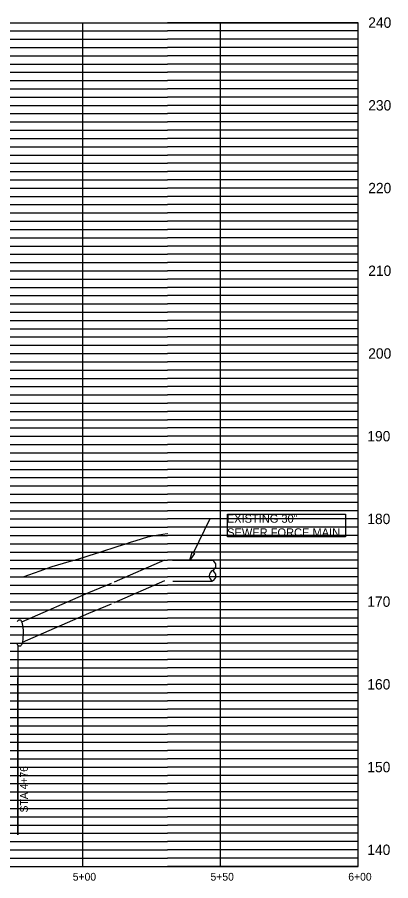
# Model space of a CAD drawing. Extents: x 1961446 to 1965364, y 798002 to 798458.
# Drawn here: x 1965228.5 to 1965364.1, y 798002.3 to 798315.4 of the extents above; entities that cross this region are included whole.
import ezdxf

# ---------------------------------------------------------------- set-up
doc = ezdxf.new("R2010")
doc.units = 0
for name, color, linetype in [('_C3D-PRSR-ANNO', 7, 'Continuous'), ('C-ANNO-SUBT', 7, 'Continuous'), ('C-GRID-MEDI', 7, 'Continuous'), ('C-GRID-THIN', 7, 'Continuous'), ('C-PROF-EXST', 7, 'Continuous'), ('C-SSWR-FMAN-FTTG', 7, 'Continuous'), ('C-SSWR-FMAN-PIPE', 7, 'Continuous'), ('C-UTIL-FITT-ANNO', 7, 'Continuous')]:
    doc.layers.add(name, color=color, linetype=linetype)

msp = doc.modelspace()

# ---------------------------------------------------------------- linework, layer by layer
at = {"layer": '_C3D-PRSR-ANNO'}
for points in [[(1965284.93, 798118.48), (1965299.41, 798118.48)], [(1965285.03, 798110.98), (1965299.41, 798110.98)]]:
    msp.add_lwpolyline(points, dxfattribs=at)
for centre, start, end in [((1965298.58, 798116.61), 293.818, 66.182), ((1965300.24, 798112.86), 113.818, 246.182), ((1965298.58, 798112.86), 293.818, 66.182)]:
    msp.add_arc(centre, 2.05, start, end, dxfattribs=at)
at = {"layer": 'C-GRID-MEDI'}
for points in [[(1964702.28, 798313.48), (1965352.28, 798313.48)], [(1964752.28, 798313.48), (1965283.11, 798313.48)], [(1965252.28, 798007.48), (1965252.28, 798313.48)], [(1965352.28, 798313.48), (1965283.11, 798313.48)], [(1965302.28, 798007.48), (1965302.28, 798313.48)], [(1965352.28, 798007.48), (1965352.28, 798313.48)], [(1965352.28, 798007.48), (1965352.28, 798313.48)], [(1964752.28, 798283.48), (1965283.11, 798283.48)], [(1965352.28, 798283.48), (1965283.11, 798283.48)], [(1964752.28, 798253.48), (1965283.11, 798253.48)], [(1965352.28, 798253.48), (1965283.11, 798253.48)], [(1964752.28, 798223.48), (1965283.11, 798223.48)], [(1965352.28, 798223.48), (1965283.11, 798223.48)], [(1964752.28, 798193.48), (1965283.11, 798193.48)], [(1965352.28, 798193.48), (1965283.11, 798193.48)], [(1964752.28, 798163.48), (1965283.11, 798163.48)], [(1965352.28, 798163.48), (1965283.11, 798163.48)], [(1964752.28, 798133.48), (1965283.11, 798133.48)], [(1965352.28, 798133.48), (1965283.11, 798133.48)], [(1964752.28, 798103.48), (1965283.11, 798103.48)], [(1965352.28, 798103.48), (1965283.11, 798103.48)], [(1964752.28, 798073.48), (1965283.11, 798073.48)], [(1965352.28, 798073.48), (1965283.11, 798073.48)], [(1964752.28, 798043.48), (1965283.11, 798043.48)], [(1965352.28, 798043.48), (1965283.11, 798043.48)], [(1964752.28, 798013.48), (1965283.11, 798013.48)], [(1965352.28, 798013.48), (1965283.11, 798013.48)], [(1964702.28, 798007.48), (1965352.28, 798007.48)], [(1964752.28, 798007.48), (1965283.11, 798007.48)], [(1965352.28, 798007.48), (1965283.11, 798007.48)]]:
    msp.add_lwpolyline(points, dxfattribs=at)
at = {"layer": 'C-GRID-THIN'}
for points in [[(1964752.28, 798310.48), (1965283.11, 798310.48)], [(1964752.28, 798307.48), (1965283.11, 798307.48)], [(1965352.28, 798310.48), (1965283.11, 798310.48)], [(1965352.28, 798307.48), (1965283.11, 798307.48)], [(1964752.28, 798304.48), (1965283.11, 798304.48)], [(1965352.28, 798304.48), (1965283.11, 798304.48)], [(1964752.28, 798301.48), (1965283.11, 798301.48)], [(1965352.28, 798301.48), (1965283.11, 798301.48)], [(1964752.28, 798298.48), (1965283.11, 798298.48)], [(1965352.28, 798298.48), (1965283.11, 798298.48)], [(1964752.28, 798295.48), (1965283.11, 798295.48)], [(1965352.28, 798295.48), (1965283.11, 798295.48)], [(1964752.28, 798292.48), (1965283.11, 798292.48)], [(1965352.28, 798292.48), (1965283.11, 798292.48)], [(1964752.28, 798289.48), (1965283.11, 798289.48)], [(1965352.28, 798289.48), (1965283.11, 798289.48)], [(1964752.28, 798286.48), (1965283.11, 798286.48)], [(1965352.28, 798286.48), (1965283.11, 798286.48)], [(1964752.28, 798280.48), (1965283.11, 798280.48)], [(1965352.28, 798280.48), (1965283.11, 798280.48)], [(1964752.28, 798277.48), (1965283.11, 798277.48)], [(1965352.28, 798277.48), (1965283.11, 798277.48)], [(1964752.28, 798274.48), (1965283.11, 798274.48)], [(1965352.28, 798274.48), (1965283.11, 798274.48)], [(1964752.28, 798271.48), (1965283.11, 798271.48)], [(1965352.28, 798271.48), (1965283.11, 798271.48)], [(1964752.28, 798268.48), (1965283.11, 798268.48)], [(1965352.28, 798268.48), (1965283.11, 798268.48)], [(1964752.28, 798265.48), (1965283.11, 798265.48)], [(1965352.28, 798265.48), (1965283.11, 798265.48)], [(1964752.28, 798262.48), (1965283.11, 798262.48)], [(1965352.28, 798262.48), (1965283.11, 798262.48)], [(1964752.28, 798259.48), (1965283.11, 798259.48)], [(1965352.28, 798259.48), (1965283.11, 798259.48)], [(1964752.28, 798256.48), (1965283.11, 798256.48)], [(1965352.28, 798256.48), (1965283.11, 798256.48)], [(1964752.28, 798250.48), (1965283.11, 798250.48)], [(1965352.28, 798250.48), (1965283.11, 798250.48)], [(1964752.28, 798247.48), (1965283.11, 798247.48)], [(1965352.28, 798247.48), (1965283.11, 798247.48)], [(1964752.28, 798244.48), (1965283.11, 798244.48)], [(1965352.28, 798244.48), (1965283.11, 798244.48)], [(1964752.28, 798241.48), (1965283.11, 798241.48)], [(1965352.28, 798241.48), (1965283.11, 798241.48)], [(1964752.28, 798238.48), (1965283.11, 798238.48)], [(1964752.28, 798235.48), (1965283.11, 798235.48)], [(1965352.28, 798238.48), (1965283.11, 798238.48)], [(1965352.28, 798235.48), (1965283.11, 798235.48)], [(1964752.28, 798232.48), (1965283.11, 798232.48)], [(1965352.28, 798232.48), (1965283.11, 798232.48)], [(1964752.28, 798229.48), (1965283.11, 798229.48)], [(1965352.28, 798229.48), (1965283.11, 798229.48)], [(1964752.28, 798226.48), (1965283.11, 798226.48)], [(1965352.28, 798226.48), (1965283.11, 798226.48)], [(1964752.28, 798220.48), (1965283.11, 798220.48)], [(1965352.28, 798220.48), (1965283.11, 798220.48)], [(1964752.28, 798217.48), (1965283.11, 798217.48)], [(1965352.28, 798217.48), (1965283.11, 798217.48)], [(1964752.28, 798214.48), (1965283.11, 798214.48)], [(1965352.28, 798214.48), (1965283.11, 798214.48)], [(1964752.28, 798211.48), (1965283.11, 798211.48)], [(1965352.28, 798211.48), (1965283.11, 798211.48)], [(1964752.28, 798208.48), (1965283.11, 798208.48)], [(1965352.28, 798208.48), (1965283.11, 798208.48)], [(1964752.28, 798205.48), (1965283.11, 798205.48)], [(1965352.28, 798205.48), (1965283.11, 798205.48)], [(1964752.28, 798202.48), (1965283.11, 798202.48)], [(1965352.28, 798202.48), (1965283.11, 798202.48)], [(1964752.28, 798199.48), (1965283.11, 798199.48)], [(1965352.28, 798199.48), (1965283.11, 798199.48)], [(1964752.28, 798196.48), (1965283.11, 798196.48)], [(1965352.28, 798196.48), (1965283.11, 798196.48)], [(1964752.28, 798190.48), (1965283.11, 798190.48)], [(1965352.28, 798190.48), (1965283.11, 798190.48)], [(1964752.28, 798187.48), (1965283.11, 798187.48)], [(1965352.28, 798187.48), (1965283.11, 798187.48)], [(1964752.28, 798184.48), (1965283.11, 798184.48)], [(1965352.28, 798184.48), (1965283.11, 798184.48)], [(1964752.28, 798181.48), (1965283.11, 798181.48)], [(1965352.28, 798181.48), (1965283.11, 798181.48)], [(1964752.28, 798178.48), (1965283.11, 798178.48)], [(1965352.28, 798178.48), (1965283.11, 798178.48)], [(1964752.28, 798175.48), (1965283.11, 798175.48)], [(1965352.28, 798175.48), (1965283.11, 798175.48)], [(1964752.28, 798172.48), (1965283.11, 798172.48)], [(1965352.28, 798172.48), (1965283.11, 798172.48)], [(1964752.28, 798169.48), (1965283.11, 798169.48)], [(1964752.28, 798166.48), (1965283.11, 798166.48)], [(1965352.28, 798169.48), (1965283.11, 798169.48)], [(1965352.28, 798166.48), (1965283.11, 798166.48)], [(1964752.28, 798160.48), (1965283.11, 798160.48)], [(1965352.28, 798160.48), (1965283.11, 798160.48)], [(1964752.28, 798157.48), (1965283.11, 798157.48)], [(1965352.28, 798157.48), (1965283.11, 798157.48)], [(1964752.28, 798154.48), (1965283.11, 798154.48)], [(1965352.28, 798154.48), (1965283.11, 798154.48)], [(1964752.28, 798151.48), (1965283.11, 798151.48)], [(1965352.28, 798151.48), (1965283.11, 798151.48)], [(1964752.28, 798148.48), (1965283.11, 798148.48)], [(1965352.28, 798148.48), (1965283.11, 798148.48)], [(1964752.28, 798145.48), (1965283.11, 798145.48)], [(1965352.28, 798145.48), (1965283.11, 798145.48)], [(1964752.28, 798142.48), (1965283.11, 798142.48)], [(1965352.28, 798142.48), (1965283.11, 798142.48)], [(1964752.28, 798139.48), (1965283.11, 798139.48)], [(1965352.28, 798139.48), (1965283.11, 798139.48)], [(1964752.28, 798136.48), (1965283.11, 798136.48)], [(1965352.28, 798136.48), (1965283.11, 798136.48)], [(1964752.28, 798130.48), (1965283.11, 798130.48)], [(1965352.28, 798130.48), (1965283.11, 798130.48)], [(1964752.28, 798127.48), (1965283.11, 798127.48)], [(1965352.28, 798127.48), (1965283.11, 798127.48)], [(1964752.28, 798124.48), (1965283.11, 798124.48)], [(1965352.28, 798124.48), (1965283.11, 798124.48)], [(1964752.28, 798121.48), (1965283.11, 798121.48)], [(1965352.28, 798121.48), (1965283.11, 798121.48)], [(1964752.28, 798118.48), (1965283.11, 798118.48)], [(1965352.28, 798118.48), (1965283.11, 798118.48)], [(1964752.28, 798115.48), (1965283.11, 798115.48)], [(1965352.28, 798115.48), (1965283.11, 798115.48)], [(1964752.28, 798112.48), (1965283.11, 798112.48)], [(1965352.28, 798112.48), (1965283.11, 798112.48)], [(1964752.28, 798109.48), (1965283.11, 798109.48)], [(1965352.28, 798109.48), (1965283.11, 798109.48)], [(1964752.28, 798106.48), (1965283.11, 798106.48)], [(1965352.28, 798106.48), (1965283.11, 798106.48)], [(1964752.28, 798100.48), (1965283.11, 798100.48)], [(1965352.28, 798100.48), (1965283.11, 798100.48)], [(1964752.28, 798097.48), (1965283.11, 798097.48)], [(1964752.28, 798094.48), (1965283.11, 798094.48)], [(1965352.28, 798097.48), (1965283.11, 798097.48)], [(1965352.28, 798094.48), (1965283.11, 798094.48)], [(1964752.28, 798091.48), (1965283.11, 798091.48)], [(1965352.28, 798091.48), (1965283.11, 798091.48)], [(1964752.28, 798088.48), (1965283.11, 798088.48)], [(1965352.28, 798088.48), (1965283.11, 798088.48)], [(1964752.28, 798085.48), (1965283.11, 798085.48)], [(1965352.28, 798085.48), (1965283.11, 798085.48)], [(1964752.28, 798082.48), (1965283.11, 798082.48)], [(1965352.28, 798082.48), (1965283.11, 798082.48)], [(1964752.28, 798079.48), (1965283.11, 798079.48)], [(1965352.28, 798079.48), (1965283.11, 798079.48)], [(1964752.28, 798076.48), (1965283.11, 798076.48)], [(1965352.28, 798076.48), (1965283.11, 798076.48)], [(1964752.28, 798070.48), (1965283.11, 798070.48)], [(1965352.28, 798070.48), (1965283.11, 798070.48)], [(1964752.28, 798067.48), (1965283.11, 798067.48)], [(1965352.28, 798067.48), (1965283.11, 798067.48)], [(1964752.28, 798064.48), (1965283.11, 798064.48)], [(1965352.28, 798064.48), (1965283.11, 798064.48)], [(1964752.28, 798061.48), (1965283.11, 798061.48)], [(1965352.28, 798061.48), (1965283.11, 798061.48)], [(1964752.28, 798058.48), (1965283.11, 798058.48)], [(1965352.28, 798058.48), (1965283.11, 798058.48)], [(1964752.28, 798055.48), (1965283.11, 798055.48)], [(1965352.28, 798055.48), (1965283.11, 798055.48)], [(1964752.28, 798052.48), (1965283.11, 798052.48)], [(1965352.28, 798052.48), (1965283.11, 798052.48)], [(1964752.28, 798049.48), (1965283.11, 798049.48)], [(1965352.28, 798049.48), (1965283.11, 798049.48)], [(1964752.28, 798046.48), (1965283.11, 798046.48)], [(1965352.28, 798046.48), (1965283.11, 798046.48)], [(1964752.28, 798040.48), (1965283.11, 798040.48)], [(1965352.28, 798040.48), (1965283.11, 798040.48)], [(1964752.28, 798037.48), (1965283.11, 798037.48)], [(1965352.28, 798037.48), (1965283.11, 798037.48)], [(1964752.28, 798034.48), (1965283.11, 798034.48)], [(1965352.28, 798034.48), (1965283.11, 798034.48)], [(1964752.28, 798031.48), (1965283.11, 798031.48)], [(1965352.28, 798031.48), (1965283.11, 798031.48)], [(1964752.28, 798028.48), (1965283.11, 798028.48)], [(1965352.28, 798028.48), (1965283.11, 798028.48)], [(1964752.28, 798025.48), (1965283.11, 798025.48)], [(1964752.28, 798022.48), (1965283.11, 798022.48)], [(1965352.28, 798025.48), (1965283.11, 798025.48)], [(1965352.28, 798022.48), (1965283.11, 798022.48)], [(1964752.28, 798019.48), (1965283.11, 798019.48)], [(1965352.28, 798019.48), (1965283.11, 798019.48)], [(1964752.28, 798016.48), (1965283.11, 798016.48)], [(1965352.28, 798016.48), (1965283.11, 798016.48)], [(1964752.28, 798010.48), (1965283.11, 798010.48)], [(1965352.28, 798010.48), (1965283.11, 798010.48)]]:
    msp.add_lwpolyline(points, dxfattribs=at)
at = {"layer": 'C-PROF-EXST'}
for points in [[(1965271.63, 798125.65), (1965275.88, 798126.96)], [(1965275.88, 798126.96), (1965278.23, 798127.48)], [(1965278.23, 798127.48), (1965282.98, 798128.16)], [(1965282.98, 798128.16), (1965283.11, 798128.13)], [(1965258.46, 798121.48), (1965265.12, 798123.6)], [(1965265.12, 798123.6), (1965267.88, 798124.48)], [(1965267.88, 798124.48), (1965269.6, 798125.03)], [(1965269.6, 798125.03), (1965271.63, 798125.65)], [(1965251.23, 798119.16), (1965256.87, 798120.98)], [(1965256.87, 798120.98), (1965258.46, 798121.48)], [(1965241.19, 798116.22), (1965245.33, 798117.41)], [(1965245.33, 798117.41), (1965249.03, 798118.48)], [(1965249.03, 798118.48), (1965249.71, 798118.68)], [(1965249.71, 798118.68), (1965251.23, 798119.16)], [(1965230.63, 798112.48), (1965236.89, 798114.72)], [(1965236.89, 798114.72), (1965239.09, 798115.48)], [(1965239.09, 798115.48), (1965241.19, 798116.22)], [(1965228.48, 798112.47), (1965230.55, 798112.47)], [(1965230.55, 798112.47), (1965230.59, 798112.47)], [(1965230.59, 798112.47), (1965230.63, 798112.48)]]:
    msp.add_lwpolyline(points, dxfattribs=at)
at = {"layer": 'C-SSWR-FMAN-FTTG'}
for points in [[(1965228.63, 798096.42), (1965228.49, 798096.12)], [(1965228.83, 798096.67), (1965228.63, 798096.42)], [(1965229.03, 798096.76), (1965228.83, 798096.67)], [(1965229.7, 798096.76), (1965229.03, 798096.76)], [(1965229.91, 798096.67), (1965229.7, 798096.76)], [(1965230.11, 798096.42), (1965229.91, 798096.67)], [(1965230.29, 798096.02), (1965230.11, 798096.42)], [(1965230.46, 798095.47), (1965230.29, 798096.02)], [(1965230.59, 798094.8), (1965230.46, 798095.47)], [(1965230.7, 798094.04), (1965230.59, 798094.8)], [(1965230.76, 798093.2), (1965230.7, 798094.04)], [(1965230.73, 798090.59), (1965230.78, 798091.45)], [(1965230.79, 798092.33), (1965230.76, 798093.2)], [(1965230.78, 798091.45), (1965230.79, 798092.33)], [(1965230.2, 798087.98), (1965230.38, 798088.45)], [(1965230.38, 798088.45), (1965230.53, 798089.06)], [(1965230.53, 798089.06), (1965230.65, 798089.78)], [(1965230.65, 798089.78), (1965230.73, 798090.59)], [(1965228.49, 798088.1), (1965228.53, 798087.98)], [(1965228.53, 798087.98), (1965228.72, 798087.65)], [(1965228.72, 798087.65), (1965228.93, 798087.48)], [(1965228.93, 798087.48), (1965229.03, 798087.48)], [(1965229.03, 798087.48), (1965229.03, 798087.46)], [(1965229.03, 798087.46), (1965229.7, 798087.46)], [(1965229.7, 798087.46), (1965229.7, 798087.48)], [(1965229.7, 798087.48), (1965229.8, 798087.48)], [(1965229.8, 798087.48), (1965230.01, 798087.65)], [(1965230.01, 798087.65), (1965230.2, 798087.98)]]:
    msp.add_lwpolyline(points, dxfattribs=at)
at = {"layer": 'C-SSWR-FMAN-PIPE'}
for points in [[(1965263.79, 798110.71), (1965282.1, 798118.67)], [(1965254.51, 798106.81), (1965262.77, 798110.21)], [(1965263.79, 798103.21), (1965282.1, 798111.17)], [(1965230.2, 798096.23), (1965254.51, 798106.81)], [(1965254.51, 798099.31), (1965262.77, 798102.71)], [(1965230.47, 798088.85), (1965254.51, 798099.31)]]:
    msp.add_lwpolyline(points, dxfattribs=at)
at = {"layer": 'C-UTIL-FITT-ANNO'}
for points in [[(1965304.89, 798135.18), (1965347.66, 798135.18), (1965347.66, 798127.03), (1965304.89, 798127.03)], [(1965292.9, 798120.95), (1965291.12, 798118.48), (1965292, 798121.39)]]:
    msp.add_lwpolyline(points, close=True, dxfattribs=at)
for points in [[(1965292.45, 798121.17), (1965298.6, 798133.65)], [(1965298.6, 798133.65), (1965302.19, 798133.65)], [(1965228.76, 798087.46), (1965228.76, 798018.97)], [(1965228.76, 798018.97), (1965228.76, 798075.83)]]:
    msp.add_lwpolyline(points, dxfattribs=at)

# ---------------------------------------------------------------- texts
at = {"layer": 'C-ANNO-SUBT'}
for s, height, p in [('240', 3.75, (1965355.91, 798311.63)), ('230', 3.75, (1965355.91, 798281.63)), ('220', 3.75, (1965355.91, 798251.63)), ('210', 3.75, (1965355.91, 798221.63)), ('200', 3.75, (1965355.91, 798191.63)), ('190', 3.75, (1965355.57, 798161.63)), ('180', 3.75, (1965355.57, 798131.63)), ('170', 3.75, (1965355.57, 798101.63)), ('160', 3.75, (1965355.57, 798071.63)), ('150', 3.75, (1965355.57, 798041.63)), ('140', 3.75, (1965355.57, 798011.63)), ('5+00', 2.814, (1965248.67, 798002.31)), ('5+50', 2.814, (1965298.67, 798002.31)), ('6+00', 2.814, (1965348.67, 798002.31))]:
    msp.add_text(s, height=height, rotation=360, dxfattribs=at).set_placement(p)
at = {"layer": 'C-UTIL-FITT-ANNO'}
for s, p in [('EXISTING 30"', (1965304.56, 798132.12)), ('SEWER FORCE MAIN', (1965304.7, 798127.08))]:
    msp.add_text(s, height=3, dxfattribs=at).set_placement(p)
msp.add_text('STA 4+76', height=2.814, rotation=90, dxfattribs=at).set_placement((1965232.37, 798027.04))

doc.saveas('drawing.dxf')
